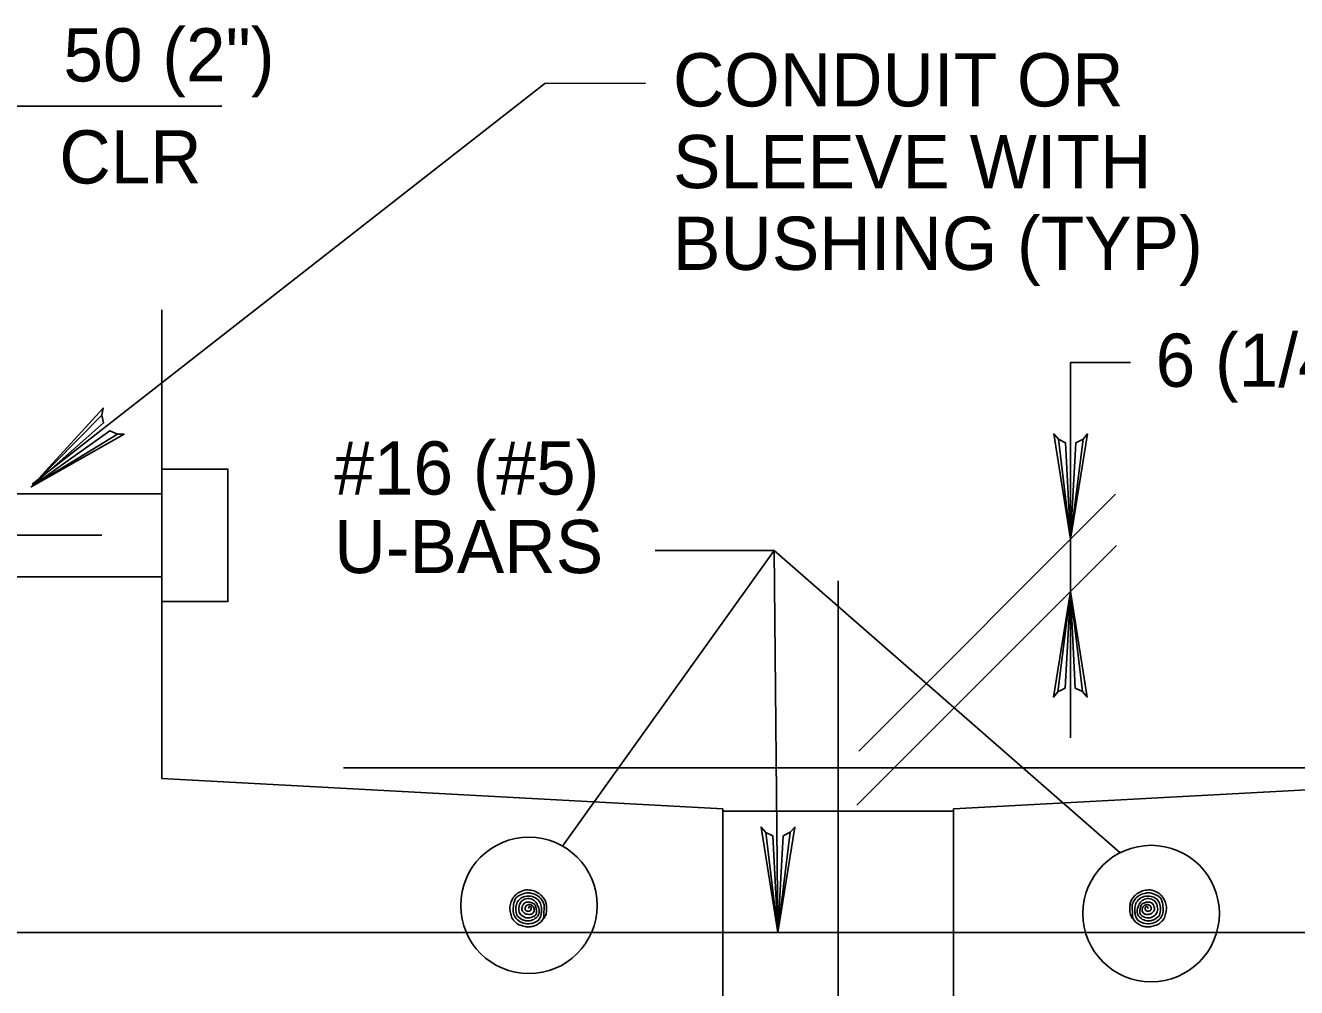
# Model space of a CAD drawing. Extents: x 638455 to 640199, y 298558 to 299152.
# Drawn here: x 638622.1 to 638702.3, y 298702.3 to 298763.1 of the extents above; entities that cross this region are included whole.
import ezdxf

# ---------------------------------------------------------------- set-up
doc = ezdxf.new("R2010")
doc.units = 0
for name, color, linetype in [('1', 7, 'Continuous'), ('2', 7, 'Continuous'), ('3', 7, 'Continuous')]:
    doc.layers.add(name, color=color, linetype=linetype)

msp = doc.modelspace()

# ---------------------------------------------------------------- linework, layer by layer
at = {"layer": '1'}
for p, q in [((638669.354, 298729.929), (638656.006, 298711.267)), ((638669.354, 298729.929), (638691.199, 298710.842)), ((638669.588, 298705.814), (638669.354, 298729.929))]:
    msp.add_line(p, q, dxfattribs=at)
for centre in [(638653.876, 298707.522), (638693.162, 298707.006)]:
    msp.add_circle(centre, 4.309, dxfattribs=at)
at = {"layer": '2'}
for p, q in [((638615.066, 298757.977), (638634.479, 298757.977)), ((638630.692, 298745.123), (638630.692, 298715.525)), ((638688.069, 298741.796), (638691.853, 298741.796)), ((638688.069, 298741.796), (638688.069, 298730.64)), ((638630.692, 298733.504), (638595.844, 298733.504)), ((638630.692, 298733.504), (638599.558, 298733.504)), ((638674.703, 298717.266), (638690.912, 298733.484)), ((638626.912, 298730.89), (638590.795, 298730.89)), ((638688.069, 298730.64), (638688.069, 298727.332)), ((638661.845, 298729.929), (638669.354, 298729.929)), ((638674.591, 298713.846), (638690.972, 298730.236)), ((638630.692, 298728.276), (638595.844, 298728.276)), ((638630.692, 298728.276), (638599.558, 298728.276)), ((638673.404, 298728.014), (638673.404, 298653.302)), ((638688.069, 298727.332), (638688.069, 298718.106)), ((638630.692, 298726.708), (638630.692, 298726.708)), ((638642.168, 298716.214), (638703.616, 298716.214)), ((638630.692, 298715.525), (638666.121, 298713.622)), ((638716.116, 298715.525), (638680.687, 298713.622)), ((638666.121, 298713.622), (638666.121, 298697.041)), ((638680.687, 298713.622), (638680.687, 298697.041)), ((638666.121, 298713.466), (638680.687, 298713.466)), ((638621.246, 298705.814), (638725.262, 298705.814))]:
    msp.add_line(p, q, dxfattribs=at)
for points in [[(638661.248, 298759.424), (638654.884, 298759.423), (638622.513, 298734.126)], [(638627.891, 298737.278), (638627.42, 298737.489), (638622.452, 298733.947), (638627.891, 298737.278), (638628.319, 298737.263), (638622.452, 298733.947), (638627.019, 298737.984), (638626.91, 298738.475), (638622.452, 298733.947), (638626.989, 298738.925), (638626.91, 298738.475)], [(638688.862, 298736.968), (638688.406, 298736.732), (638688.069, 298730.64), (638688.862, 298736.968), (638689.141, 298737.293), (638688.069, 298730.64), (638687.767, 298736.726), (638687.314, 298736.95), (638688.069, 298730.64), (638687.012, 298737.293), (638687.314, 298736.95)], [(638687.273, 298721.001), (638687.732, 298721.239), (638688.069, 298727.332), (638687.273, 298721.001), (638686.998, 298720.679), (638688.069, 298727.332), (638688.371, 298721.242), (638688.824, 298721.022), (638688.069, 298727.332), (638689.126, 298720.679), (638688.824, 298721.022)], [(638670.381, 298712.145), (638669.925, 298711.91), (638669.588, 298705.814), (638670.381, 298712.145), (638670.659, 298712.47), (638669.588, 298705.814), (638669.286, 298711.904), (638668.833, 298712.128), (638669.588, 298705.814), (638668.531, 298712.47), (638668.833, 298712.128)]]:
    msp.add_lwpolyline(points, dxfattribs=at)
msp.add_lwpolyline([(638630.692, 298726.708), (638630.692, 298735.072), (638634.874, 298735.072), (638634.874, 298726.708)], close=True, dxfattribs=at)
for points in [[(638653.842, 298707.327), (638653.9, 298707.443), (638653.987, 298707.431), (638654.007, 298707.248), (638653.845, 298707.15), (638653.65, 298707.248), (638653.659, 298707.431), (638653.767, 298707.542), (638653.987, 298707.559), (638654.141, 298707.443), (638654.217, 298707.257), (638654.103, 298707.007), (638653.862, 298706.952), (638653.595, 298707.033), (638653.453, 298707.202), (638653.47, 298707.486), (638653.604, 298707.669), (638653.845, 298707.739), (638654.06, 298707.692), (638654.237, 298707.585), (638654.315, 298707.399), (638654.359, 298707.158), (638654.304, 298706.934), (638654.095, 298706.792), (638653.775, 298706.728), (638653.427, 298706.874), (638653.253, 298707.112), (638653.253, 298707.443), (638653.363, 298707.725), (638653.604, 298707.91), (638653.987, 298707.934), (638654.26, 298707.783), (638654.426, 298707.518), (638654.524, 298707.248), (638654.478, 298706.917), (638654.26, 298706.685), (638653.944, 298706.551), (638653.439, 298706.633), (638653.122, 298706.908), (638653.055, 298707.292), (638653.122, 298707.669), (638653.343, 298707.965), (638653.636, 298708.085), (638654.095, 298708.076), (638654.458, 298707.867), (638654.632, 298707.559), (638654.675, 298707.234), (638654.644, 298706.952), (638654.533, 298706.65), (638654.237, 298706.435), (638653.758, 298706.368), (638653.328, 298706.487), (638653.011, 298706.783), (638652.881, 298707.132), (638652.913, 298707.573), (638653.055, 298707.989), (638653.296, 298708.16), (638653.72, 298708.314), (638654.161, 298708.25), (638654.469, 298708.108), (638654.708, 298707.835), (638654.832, 298707.55), (638654.832, 298707.248), (638654.818, 298706.917), (638654.742, 298706.609), (638654.586, 298706.435), (638654.345, 298706.284), (638654.103, 298706.194), (638653.862, 298706.159), (638653.561, 298706.203), (638653.253, 298706.302), (638652.989, 298706.496), (638652.805, 298706.746), (638652.718, 298707.059), (638652.672, 298707.353), (638652.739, 298707.692), (638652.86, 298707.965), (638653.078, 298708.215), (638653.343, 298708.384), (638653.604, 298708.482), (638653.918, 298708.491), (638654.284, 298708.401), (638654.586, 298708.215), (638654.774, 298708.018), (638654.928, 298707.768), (638654.983, 298707.507), (638654.992, 298707.202), (638654.928, 298706.874), (638654.832, 298706.72), (638654.632, 298706.496)], [(638692.965, 298707.327), (638692.907, 298707.443), (638692.82, 298707.431), (638692.8, 298707.248), (638692.962, 298707.15), (638693.157, 298707.248), (638693.148, 298707.431), (638693.041, 298707.542), (638692.82, 298707.559), (638692.666, 298707.443), (638692.59, 298707.257), (638692.704, 298707.007), (638692.945, 298706.952), (638693.212, 298707.033), (638693.354, 298707.202), (638693.337, 298707.486), (638693.203, 298707.669), (638692.962, 298707.739), (638692.747, 298707.692), (638692.57, 298707.585), (638692.492, 298707.399), (638692.448, 298707.158), (638692.504, 298706.934), (638692.713, 298706.792), (638693.032, 298706.728), (638693.381, 298706.874), (638693.555, 298707.112), (638693.555, 298707.443), (638693.444, 298707.725), (638693.203, 298707.91), (638692.82, 298707.934), (638692.547, 298707.783), (638692.381, 298707.518), (638692.283, 298707.248), (638692.329, 298706.917), (638692.547, 298706.685), (638692.864, 298706.551), (638693.369, 298706.633), (638693.685, 298706.908), (638693.752, 298707.292), (638693.685, 298707.669), (638693.464, 298707.965), (638693.171, 298708.085), (638692.713, 298708.076), (638692.35, 298707.867), (638692.175, 298707.559), (638692.132, 298707.234), (638692.163, 298706.952), (638692.274, 298706.65), (638692.57, 298706.435), (638693.049, 298706.368), (638693.479, 298706.487), (638693.796, 298706.783), (638693.926, 298707.132), (638693.894, 298707.573), (638693.752, 298707.989), (638693.511, 298708.16), (638693.087, 298708.314), (638692.646, 298708.25), (638692.338, 298708.108), (638692.1, 298707.835), (638691.975, 298707.55), (638691.975, 298707.248), (638691.989, 298706.917), (638692.065, 298706.609), (638692.221, 298706.435), (638692.463, 298706.284), (638692.704, 298706.194), (638692.945, 298706.159), (638693.247, 298706.203), (638693.555, 298706.302), (638693.819, 298706.496), (638694.002, 298706.746), (638694.089, 298707.059), (638694.135, 298707.353), (638694.069, 298707.692), (638693.947, 298707.965), (638693.729, 298708.215), (638693.464, 298708.384), (638693.203, 298708.482), (638692.889, 298708.491), (638692.524, 298708.401), (638692.221, 298708.215), (638692.033, 298708.018), (638691.879, 298707.768), (638691.824, 298707.507), (638691.815, 298707.202), (638691.879, 298706.874), (638691.975, 298706.72), (638692.175, 298706.496)]]:
    msp.add_spline(points, degree=3, dxfattribs=at)

# ---------------------------------------------------------------- texts
at = {"layer": '3'}
for s, p in [('50 (2")', (638624.482, 298759.541)), ('CONDUIT OR', (638662.973, 298757.965)), ('CLR', (638624.224, 298753.1)), ('SLEEVE WITH', (638662.973, 298752.805)), ('BUSHING (TYP)', (638662.973, 298747.645)), ('6 (1/4")', (638693.45, 298740.264)), ('#16 (#5)', (638641.588, 298733.459)), ('U-BARS', (638641.588, 298728.499))]:
    msp.add_text(s, height=3.36, dxfattribs=at).set_placement(p)

doc.saveas('drawing.dxf')
